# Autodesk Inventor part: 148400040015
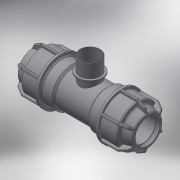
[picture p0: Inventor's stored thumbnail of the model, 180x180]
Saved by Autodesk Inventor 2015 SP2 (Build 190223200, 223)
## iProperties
Created: 2017-08
Part Number: 148400040015
Material: Generic
Description: PLASSON L.14 TEE MALE ADAPTOR (SILVER) 40-1.1/2"-40
Document SubType Name: Modeling
Designer: KIM
Density: 1 g/cm^3
Appearance: Default
Author: KIM
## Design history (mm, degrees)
derived "148400.ipt"
feature "Solid1::148400.ipt"
feature "Solid2::148400.ipt"
tag "TaggingFeature1"
body "Solid1"
body "Solid2"
other parameters: "d2" = 62, "d4" = 15 deg, "d5" = 40.92, "d6" = 13.5036, "d10" = 73, "d16" = 40.8, "d17" = 3.1, "d22" = 64, "d24" = 3.1, "d25" = 65.7, "d26" = 54.75, "d27" = 3.1, "d28" = 135 deg, "d29" = 1.86, "d31" = 2, "d46" = 150 deg, "d49" = 3.65, "d50" = 0, "d58" = 1.2, "d61" = 360 deg, "d63" = 36, "d64" = 86.5, "d80" = 57.6, "d81" = 3.2, "d84" = 3.1, "d94" = 69, "d96" = 47.803, "d108" = 1.2, "d111" = 0, "d113" = 36, "d114" = 57.3636, "d115" = 22, "d116" = 2.2, "d117" = 47.803, "R_" = 47.803, "E_" = 73, "H_" = 173, "l_" = 62, "l_2" = 22, "A_" = 69
